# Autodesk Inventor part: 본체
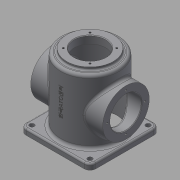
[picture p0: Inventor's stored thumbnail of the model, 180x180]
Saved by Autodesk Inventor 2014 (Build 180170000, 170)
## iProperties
Created: 2015-10
Part Number: 본체
Material: 일반
Document SubType Name: Modeling
Designer: USER
Density: 1 g/cm^3
Appearance: 기본값
Author: USER
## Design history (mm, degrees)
sketch "스케치1"
  geometry: L1 (0, 0)-(50, 0); L2 (50, 0)-(50, 110); L3 (50, 110)-(0, 110); L4 (0, 110)-(0, 0)
  constraints: 8 end point, 2 parallel, 1 horizontal, 1 perpendicular
  dimensions: "d1" = 100 diameter of L2 L4; "d2" = 110 distance of L1.end L2.end
revolve "회전1" sketch "스케치1" stored, may be unused: angle "d3" = 90 deg
sketch "스케치2"
  geometry: C1 r 50 at (0, 0) reference; C2 r 40 at (0, 0)
  constraints: 1 centre point, 1 coincident
  dimensions: "d4" = 80 diameter of C2
extrude "돌출1" join sketch "스케치2" distance "d5" = 5; taper "d6" = 0 deg
sketch "스케치3"
  geometry: L1 (-60, 0)-(60, 0); L2 (60, 0)-(60, -10); L3 (60, -10)-(-60, -10); L4 (-60, -10)-(-60, 0); 2 further points
  constraints: 8 end point, 2 midpoint, 2 parallel, 1 coincident, 1 horizontal, 1 perpendicular
  dimensions: "d7" = 10 distance of L1.end L2.end; "d8" = 120 distance of L2.end L3.end
extrude "돌출2" join sketch "스케치3" stored distance "d9" = 120; taper "d10" = 0 deg
fillet "모깎기1" dims "d11" = 10
fillet "모깎기2" dims "d12" = 3
hole "구멍1" diameter "d15" = 8; stored, may be unused: countersink angle "d19" = 90 deg, drill point angle "d21" = 118 deg; dims "d13" = 10, "d14" = 10, "d16" = 6, "d17" = 4, "d18" = 2, "d20" = 8
fillet "모깎기3" dims "d22" = 5
hole "구멍2" diameter "d25" = 54; stored, may be unused: countersink angle "d29" = 90 deg, drill point angle "d31" = 118 deg; dims "d23" = 10, "d24" = 10, "d26" = 6, "d27" = 4, "d28" = 2, "d30" = 8
hole "구멍3" diameter "d34" = 90; stored, may be unused: countersink angle "d38" = 90 deg, drill point angle "d40" = 0 deg; dims "d32" = 10, "d33" = 10, "d35" = 6, "d36" = 4, "d37" = 2, "d39" = 112
chamfer "모따기1" distance "d41" = 3; stored, may be unused: second distance "d42" = 2, angle "d43" = 45 deg
fillet "모깎기4" dims "d44" = 5
fillet "모깎기5" dims "d45" = 3
chamfer "모따기2" distance "d46" = 1; stored, may be unused: second distance "d47" = 2, angle "d48" = 45 deg
fillet "모깎기6" dims "d49" = 3
sketch "스케치4"
  geometry: L1 (-41.366, 41.366)-(0, 0); L2 (0, 0)-(-87.056, 0); C1 r 40 at (0, 0) reference; C2 r 28 at (0, 0) reference; 1 further point
  constraints: 4 end point, 1 horizontal, 1 point on line
  dimensions: "d50" = 45 deg angle of L2 L1; "d51" = 32.5 distance of C1.centre point (-22.981, 22.981)
hole "구멍4" sketch "스케치4" at (-22.981, 22.981) diameter "d52" = 3.242; stored, may be unused: countersink angle "d56" = 90 deg, drill point angle "d58" = 118 deg; dims "d53" = 8, "d54" = 4, "d55" = 2, "d57" = 10
node "작업 평면2"
  node "작업 평면1"
sketch "스케치5"
  geometry: L1 (-50, -65)-(50, -65) reference; L2 (40, 60)-(-40, 60) reference; 3 further points
  constraints: 1 midpoint, 1 vertical alignment, 1 other
  dimensions: "d63" = 70 distance from line of L1 point (0, 5)
feature "엠보싱1" sketch "스케치5" dims "d1" = 100, "d2" = 110, "d64" = 0.5, "d65" = 0
sketch "스케치6"
  geometry: L1 (-62, 90)-(62, 90); L2 (62, 90)-(62, 50); L3 (62, 50)-(-62, 50); L4 (-62, 50)-(-62, 90); L5 (60, -10)-(50, -10) reference; 2 further points
  constraints: 8 end point, 2 parallel, 1 horizontal, 1 midpoint, 1 perpendicular, 1 vertical alignment
  dimensions: "d66" = 60 distance from line of L5 L2.end; "d67" = 80 diameter of L1 L3; "d68" = 124 distance of L1.start L1.end
revolve "회전2" sketch "스케치6" stored, may be unused: angle "d69" = 90 deg
fillet "모깎기7" dims "d70" = 5
hole "구멍5" diameter "d73" = 54; stored, may be unused: countersink angle "d77" = 90 deg, drill point angle "d79" = 118 deg; dims "d71" = 10, "d72" = 10, "d74" = 8, "d75" = 4, "d76" = 2, "d78" = 10
chamfer "모따기3" distance "d80" = 1; stored, may be unused: second distance "d81" = 2, angle "d82" = 45 deg
hole "구멍6" diameter "d85" = 90; stored, may be unused: countersink angle "d89" = 90 deg, drill point angle "d91" = 0 deg; dims "d83" = 10, "d84" = 10, "d86" = 8, "d87" = 4, "d88" = 2, "d90" = 112
fillet "모깎기8" dims "d92" = 3
fillet "모깎기9" dims "d93" = 3
sketch "스케치7"
  geometry: C1 r 40 at (0, 0) reference; 2 further points
  constraints: 1 vertical alignment
  dimensions: "d94" = 32.5 distance of C1.centre point (0, 32.5)
hole "구멍7" sketch "스케치7" at (0, 32.5) diameter "d95" = 3.242; stored, may be unused: countersink angle "d99" = 90 deg, drill point angle "d101" = 118 deg; dims "d96" = 8, "d97" = 4, "d98" = 2, "d100" = 10
node "솔리드1"
mirror "대칭1"
mirror "대칭2"
pattern_circular "원형 패턴1" dims angle "d60" = 360 deg
pattern_circular "원형 패턴2" dims angle "d103" = 360 deg
mirror "대칭3"
other parameters: "d62" = 0.5
